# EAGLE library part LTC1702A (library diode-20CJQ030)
Linear Tech's LTC1702A Dual 550kHz Synchronous 2-Phase Switching Regulator Controller Description: The LTC®1702A is a dual switching regulator controller optimized for high efficiency with low input voltages. It includes two complete, on-chip, independent switching regulator controllers each designed to drive a pair of external Nchannel MOSFETs in a voltage mode feedback, synchronous buck configuration. The LTC1702A uses a constant-frequency, true PWM design switching at 550kHz, minimizing external component size and cost and maximizing load transient performance. The synchronous buck architecture automatically shifts to discontinuous and then to Burst Mode® operation as the output load decreases, ensuring maximum efficiency over a wide range of load currents. The LTC1702A features an onboard reference trimmed to 0.5% and can provide better than 1% regulation at the converter outputs. Open-drain logic outputs indicate whether either output has risen to within 5% of the final output voltage and an optional latching FAULT mode protects the load if the output rises 15% above the intended voltage. Each channel can be enabled independently; with both channels disabled, the LTC1702A shuts down and supply current drops below 100mA. Features: Pin Compatible with the LTC1702 with Improved Current Limit Control Two Sides Run Out-of-Phase to Minimize CIN No External Current Sense Resistors Excellent Output Regulation: 1% Total Output Accuracy Two Independent Controllers in One Package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
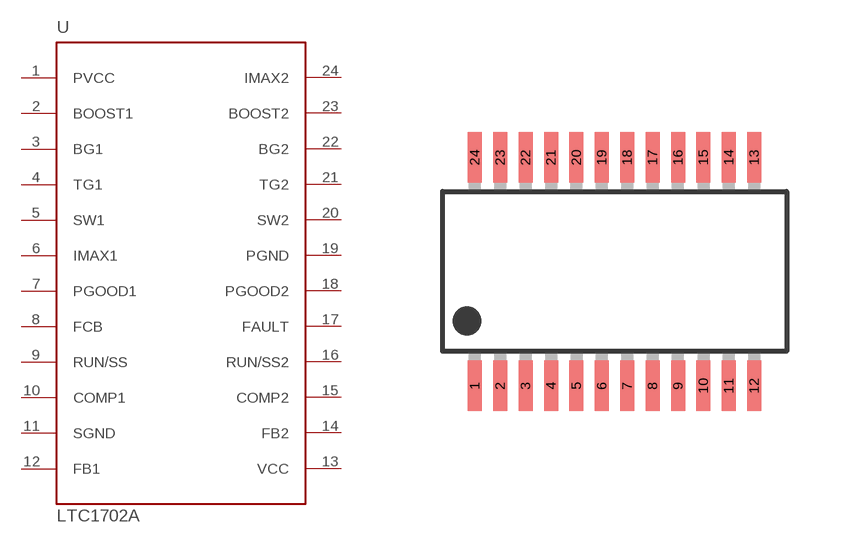
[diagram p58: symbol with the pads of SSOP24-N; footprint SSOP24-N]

Designator prefix U

## LTC1702A  [SSOP24-N]
1  PVCC  pwr
2  BOOST1  in
3  BG1  out
4  TG1  out
5  SW1  out
6  IMAX1  in
7  PGOOD1  out
8  FCB  in
9  RUN/SS  in
10  COMP1  in
11  SGND  pwr
12  FB1  in
13  VCC  pwr
14  FB2  in
15  COMP2  in
16  RUN/SS2  in
17  FAULT  out
18  PGOOD2  out
19  PGND  pwr
20  SW2  out
21  TG2  out
22  BG2  out
23  BOOST2  in
24  IMAX2  in

## Footprint SSOP24-N (pad centres in mm)
SSOP24 Narrow E.g.: LTC1702
smd 0.35 x 1.27: 1 -3.493,-2.857; 2 -2.857,-2.857; 3 -2.223,-2.857; 4 -1.587,-2.857; 5 -0.953,-2.857; 6 -0.318,-2.857; 7 0.318,-2.857; 8 0.953,-2.857; 9 1.587,-2.857; 10 2.223,-2.857; 11 2.857,-2.857; 12 3.493,-2.857; 13 3.493,2.857; 14 2.857,2.857; 15 2.223,2.857; 16 1.587,2.857; 17 0.953,2.857; 18 0.318,2.857; 19 -0.318,2.857; 20 -0.953,2.857; 21 -1.587,2.857; 22 -2.223,2.857; 23 -2.857,2.857; 24 -3.493,2.857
